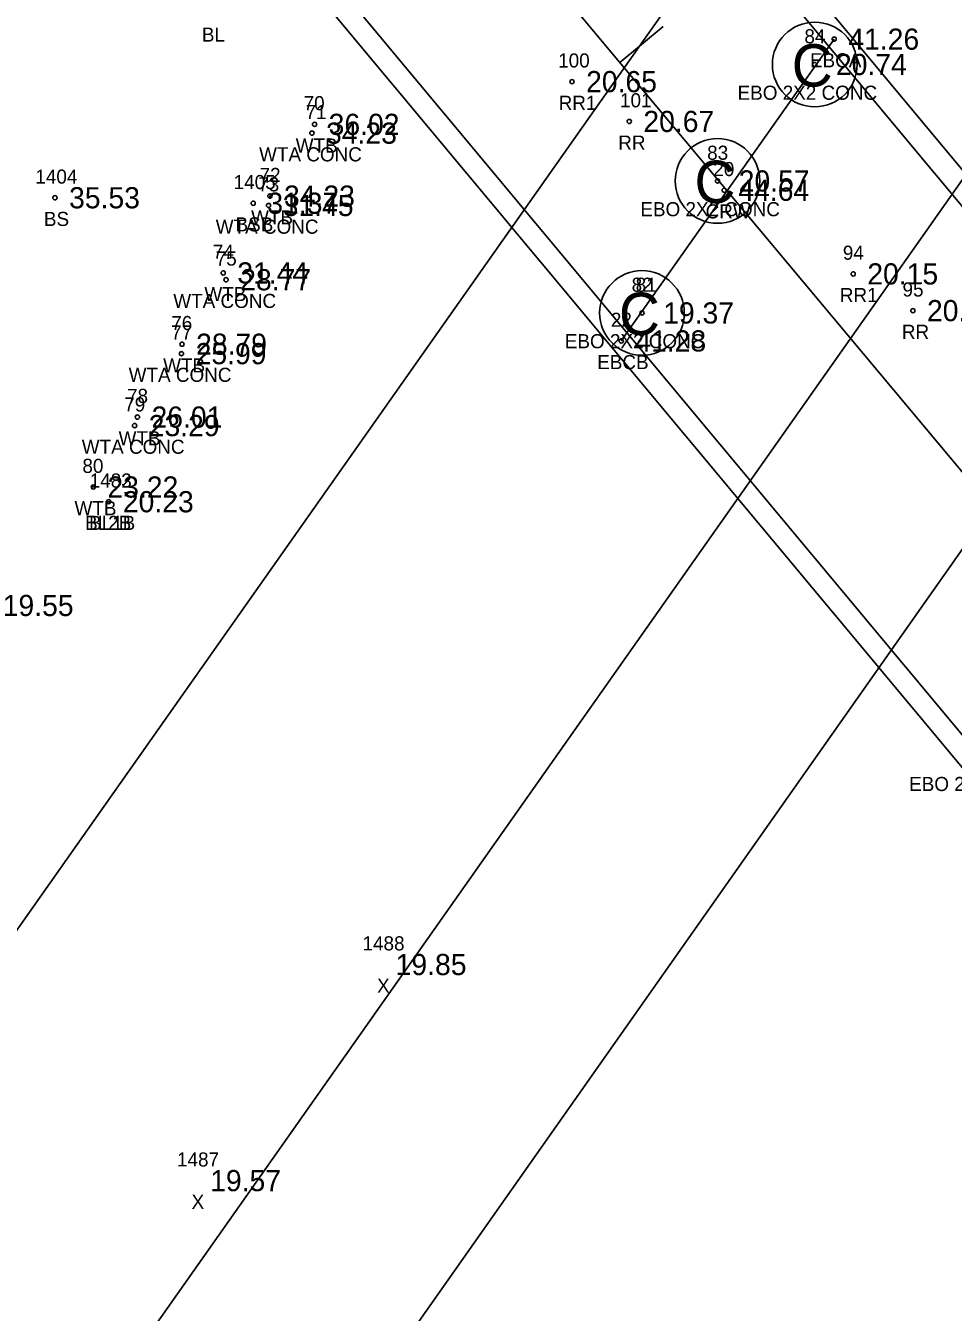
# Model space of a CAD drawing. Extents: x 2042117 to 2045853, y 303080 to 309569.
# Drawn here: x 2043426.9 to 2043492.6, y 305813.6 to 305904.8 of the extents above; entities that cross this region are included whole.
import ezdxf

# ---------------------------------------------------------------- set-up
doc = ezdxf.new("R2010")
doc.units = 0
for name, color, linetype in [('RD_DTM_BkLn_txCode', 7, 'Continuous'), ('RD_EX_Bridge', 7, 'Continuous'), ('RD_EX_Bridge_txCode', 7, 'Continuous'), ('RD_EX_Misc_txCode', 7, 'Continuous'), ('RD_EX_RailRoad', 7, 'Continuous'), ('RD_EX_RailRoad_txCode', 7, 'Continuous'), ('RD_EX_TX_Bridge_ELEV', 7, 'Continuous'), ('RD_EX_TX_Misc_ELEV', 7, 'Continuous'), ('RD_EX_TX_RailRoad_ELEV', 7, 'Continuous'), ('RD_EX_UT', 7, 'Continuous'), ('RD_HC_Cl', 7, 'Continuous'), ('RD_HC_Data_Tic', 7, 'Continuous'), ('RD_HC_Survey_ELEV', 7, 'Continuous'), ('RD_HC_Survey_txCode', 7, 'Continuous'), ('RD_SMD_Locator', 7, 'Continuous')]:
    doc.layers.add(name, color=color, linetype=linetype)

msp = doc.modelspace()

# ---------------------------------------------------------------- linework, layer by layer
at = {"layer": 'RD_EX_Bridge'}
msp.add_line((2043484.122, 305903.82), (2043469.037, 305882.434), dxfattribs=at)
msp.add_lwpolyline([(2043457.568, 305934.733), (2043443.332, 305914.368), (2043521.862, 305820.103), (2043536.154, 305840.416), (2043457.568, 305934.733)], dxfattribs=at)
for centre in [(2043482.744, 305902.022), (2043475.857, 305893.77), (2043470.507, 305884.417), (2043470.507, 305884.417)]:
    msp.add_circle(centre, 3, dxfattribs=at)
at = {"layer": 'RD_EX_RailRoad'}
for points in [[(2043319.014, 305688.393), (2043467.578, 305899.398), (2043576.811, 306054.414)], [(2043364.311, 305710.833), (2043487.579, 305885.883), (2043596.31, 306040.356)], [(2043376.842, 305702.303), (2043499.952, 305877.288), (2043608.717, 306031.564)]]:
    msp.add_lwpolyline(points, dxfattribs=at)
at = {"layer": 'RD_EX_UT'}
msp.add_line((2043443.493, 305911.856), (2043519.608, 305820.486), dxfattribs=at)
msp.add_lwpolyline([(2043462.272, 305936.284), (2043464.785, 305928.69), (2043533.857, 305845.732), (2043538.199, 305846.313)], dxfattribs=at)
at = {"layer": 'RD_HC_Cl'}
msp.add_line((2043284.298, 306123.239), (2045221.309, 303803.998), dxfattribs=at)
at = {"layer": 'RD_HC_Data_Tic'}
msp.add_line((2043468.946, 305902.155), (2043472.016, 305904.719), dxfattribs=at)
at = {"layer": 'RD_SMD_Locator'}
for centre in [(2043484.122, 305903.82), (2043482.744, 305902.022), (2043465.55, 305900.809), (2043447.316, 305897.782), (2043469.606, 305897.987), (2043447.13, 305897.158), (2043475.857, 305893.77), (2043428.932, 305892.58), (2043444.155, 305892.698), (2043476.331, 305893.112), (2043442.974, 305892.193), (2043444.06, 305892.032), (2043440.849, 305887.254), (2043441.054, 305886.772), (2043485.465, 305887.185), (2043470.507, 305884.417), (2043470.507, 305884.417), (2043489.692, 305884.581), (2043437.928, 305882.203), (2043469.037, 305882.434), (2043437.895, 305881.534), (2043434.771, 305877.04), (2043434.573, 305876.436), (2043431.65, 305872.083), (2043432.741, 305871.042), (2043432.741, 305871.042)]:
    msp.add_circle(centre, 0.15, dxfattribs=at)

# ---------------------------------------------------------------- texts
at = {"layer": 'RD_DTM_BkLn_txCode'}
for s, p in [('BL', (2043439.34, 305903.64)), ('1404', (2043427.546, 305893.58)), ('1405', (2043441.588, 305893.193)), ('BS', (2043428.152, 305890.58)), ('BSB', (2043441.722, 305890.193)), ('1482', (2043431.395, 305872.042)), ('1483', (2043431.395, 305872.042)), ('BL2B', (2043431.064, 305869.042)), ('BL1B', (2043431.347, 305869.042))]:
    msp.add_text(s, height=1, dxfattribs=at).set_placement(p)
at = {"layer": 'RD_EX_Bridge'}
for p in [(2043481.113, 305900.461), (2043474.226, 305892.208), (2043468.876, 305882.855), (2043468.876, 305882.855)]:
    msp.add_text('C', height=3, dxfattribs=at).set_placement(p)
at = {"layer": 'RD_EX_Bridge_txCode'}
for s, p in [('84', (2043482.011, 305903.522)), ('EBCA', (2043482.405, 305901.82)), ('EBO 2X2 CONC', (2043477.279, 305899.522)), ('83', (2043475.125, 305895.27)), ('EBO 2X2 CONC', (2043470.393, 305891.27)), ('82', (2043469.774, 305885.917)), ('81', (2043470.058, 305885.917)), ('22', (2043468.305, 305883.434)), ('EBO 2X2 CONC', (2043465.042, 305881.917)), ('EBO 2X2 CONC', (2043465.042, 305881.917)), ('EBCB', (2043467.336, 305880.434)), ('EBO 2X2 CONCRETE', (2043489.427, 305850.541))]:
    msp.add_text(s, height=1, dxfattribs=at).set_placement(p)
at = {"layer": 'RD_EX_Misc_txCode'}
for s, p in [('70', (2043446.544, 305898.782)), ('71', (2043446.681, 305898.158)), ('WTA CONC', (2043443.39, 305895.158)), ('WTB', (2043445.985, 305895.782)), ('72', (2043443.423, 305893.698)), ('73', (2043443.328, 305893.032)), ('WTB', (2043442.824, 305890.698)), ('WTA CONC', (2043440.32, 305890.032)), ('74', (2043440.116, 305888.254)), ('75', (2043440.321, 305887.772)), ('WTB', (2043439.518, 305885.254)), ('WTA CONC', (2043437.314, 305884.772)), ('76', (2043437.172, 305883.203)), ('77', (2043437.163, 305882.534)), ('WTA CONC', (2043434.155, 305879.534)), ('WTB', (2043436.597, 305880.203)), ('78', (2043434.039, 305878.04)), ('79', (2043433.84, 305877.436)), ('WTB', (2043433.44, 305875.04)), ('WTA CONC', (2043430.832, 305874.436)), ('80', (2043430.878, 305873.083)), ('WTB', (2043430.319, 305870.083)), ('1488', (2043450.716, 305839.247)), ('X', (2043451.747, 305836.247)), ('1487', (2043437.579, 305823.935)), ('X', (2043438.61, 305820.935))]:
    msp.add_text(s, height=1, dxfattribs=at).set_placement(p)
at = {"layer": 'RD_EX_RailRoad_txCode'}
for s, p in [('100', (2043464.573, 305901.809)), ('RR1', (2043464.605, 305898.809)), ('101', (2043468.953, 305898.987)), ('RR', (2043468.827, 305895.987)), ('94', (2043484.733, 305888.185)), ('RR1', (2043484.52, 305885.185)), ('95', (2043488.96, 305885.581)), ('RR', (2043488.913, 305882.581))]:
    msp.add_text(s, height=1, dxfattribs=at).set_placement(p)
at = {"layer": 'RD_EX_TX_Bridge_ELEV'}
for s, p in [('41.26', (2043485.122, 305903.07)), ('20.74', (2043484.244, 305901.272)), ('20.57', (2043477.357, 305893.02)), ('19.37', (2043472.007, 305883.667)), ('19.37', (2043472.007, 305883.667)), ('41.28', (2043470.037, 305881.684))]:
    msp.add_text(s, height=1.5, dxfattribs=at).set_placement(p)
at = {"layer": 'RD_EX_TX_Misc_ELEV'}
for s, p in [('34.23', (2043448.13, 305896.408)), ('36.02', (2043448.316, 305897.032)), ('35.53', (2043429.932, 305891.83)), ('34.23', (2043445.155, 305891.948)), ('31.37', (2043443.974, 305891.443)), ('31.45', (2043445.06, 305891.282)), ('31.44', (2043441.849, 305886.504)), ('28.77', (2043442.054, 305886.022)), ('28.79', (2043438.928, 305881.453)), ('25.99', (2043438.895, 305880.784)), ('26.01', (2043435.771, 305876.29)), ('23.29', (2043435.573, 305875.686)), ('23.22', (2043432.65, 305871.333)), ('20.23', (2043433.741, 305870.292)), ('20.23', (2043433.741, 305870.292)), ('19.55', (2043425.234, 305862.94)), ('19.85', (2043453.062, 305837.497)), ('19.57', (2043439.925, 305822.185))]:
    msp.add_text(s, height=1.5, dxfattribs=at).set_placement(p)
at = {"layer": 'RD_EX_TX_RailRoad_ELEV'}
for s, p in [('20.65', (2043466.55, 305900.059)), ('20.67', (2043470.606, 305897.237)), ('20.15', (2043486.465, 305886.435)), ('20.15', (2043490.692, 305883.831))]:
    msp.add_text(s, height=1.5, dxfattribs=at).set_placement(p)
at = {"layer": 'RD_HC_Survey_ELEV'}
msp.add_text('44.64', height=1.5, dxfattribs=at).set_placement((2043477.331, 305892.362))
at = {"layer": 'RD_HC_Survey_txCode'}
for s, p in [('20', (2043475.559, 305894.112)), ('CRW', (2043475.016, 305891.112))]:
    msp.add_text(s, height=1, dxfattribs=at).set_placement(p)

doc.saveas('drawing.dxf')
